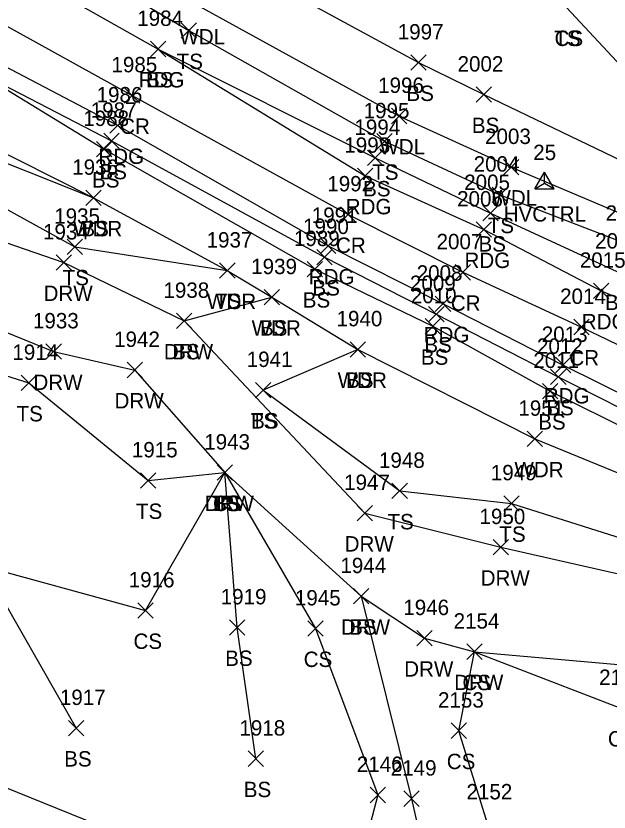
# Model space of a CAD drawing. Extents: x 1512665 to 1513714, y 110636 to 112816.
# Drawn here: x 1512837.5 to 1512914.5, y 110765.6 to 110869.1 of the extents above; entities that cross this region are included whole.
import ezdxf

# ---------------------------------------------------------------- set-up
doc = ezdxf.new("R2010")
doc.units = 0
for name, color, linetype in [('C_A', 7, 'Continuous'), ('C_I', 7, 'Continuous'), ('CPSM', 7, 'Continuous'), ('L_A', 7, 'Continuous'), ('L_I', 7, 'Continuous'), ('L_TIC', 7, 'Continuous'), ('LAWA', 7, 'Continuous'), ('LELB', 7, 'Continuous'), ('LSOGP', 7, 'Continuous'), ('P_A', 7, 'Continuous'), ('P_I', 7, 'Continuous'), ('P_TIC', 7, 'Continuous'), ('PEU', 7, 'Continuous'), ('PRC', 7, 'Continuous'), ('R_A', 7, 'Continuous'), ('R_I', 7, 'Continuous'), ('R_TIC', 7, 'Continuous'), ('RDW', 7, 'Continuous')]:
    doc.layers.add(name, color=color, linetype=linetype)

msp = doc.modelspace()

# ---------------------------------------------------------------- linework, layer by layer
at = {"layer": 'CPSM'}
for p, q in [((1512904.88, 110846.67), (1512906.13, 110848.84)), ((1512907.38, 110846.67), (1512906.13, 110848.84)), ((1512906.13, 110847.4), (1512906.13, 110848.84)), ((1512904.88, 110846.67), (1512906.13, 110847.4)), ((1512906.13, 110847.4), (1512906.13, 110847.4)), ((1512906.13, 110847.4), (1512907.38, 110846.67)), ((1512904.88, 110846.67), (1512907.38, 110846.67))]:
    msp.add_line(p, q, dxfattribs=at)
at = {"layer": 'L_TIC'}
for points in [[(1512858.93, 110866.23), (1512860.93, 110868.23)], [(1512860.93, 110866.23), (1512858.93, 110868.23)], [(1512854.92, 110863.84), (1512856.92, 110865.84)], [(1512856.92, 110863.84), (1512854.92, 110865.84)], [(1512888.75, 110862.08), (1512890.75, 110864.08)], [(1512890.75, 110862.08), (1512888.75, 110864.08)], [(1512897.25, 110857.91), (1512899.25, 110859.91)], [(1512899.25, 110857.91), (1512897.25, 110859.91)], [(1512886.26, 110855.13), (1512888.26, 110857.13)], [(1512888.26, 110855.13), (1512886.26, 110857.13)], [(1512848.87, 110851.9), (1512850.87, 110853.9)], [(1512850.87, 110851.9), (1512848.87, 110853.9)], [(1512884.33, 110851.84), (1512886.33, 110853.84)], [(1512886.33, 110851.84), (1512884.33, 110853.84)], [(1512847.91, 110850.83), (1512849.91, 110852.83)], [(1512849.91, 110850.83), (1512847.91, 110852.83)], [(1512883.12, 110849.68), (1512885.12, 110851.68)], [(1512885.12, 110849.68), (1512883.12, 110851.68)], [(1512900.81, 110848.49), (1512902.81, 110850.49)], [(1512902.81, 110848.49), (1512900.81, 110850.49)], [(1512846.52, 110844.49), (1512848.52, 110846.49)], [(1512848.52, 110844.49), (1512846.52, 110846.49)], [(1512846.52, 110844.49), (1512848.52, 110846.49)], [(1512848.52, 110844.49), (1512846.52, 110846.49)], [(1512899.34, 110844.9), (1512901.34, 110846.9)], [(1512901.34, 110844.9), (1512899.34, 110846.9)], [(1512898.11, 110842.51), (1512900.11, 110844.51)], [(1512900.11, 110842.51), (1512898.11, 110844.51)], [(1512844.12, 110838.12), (1512846.12, 110840.12)], [(1512846.12, 110838.12), (1512844.12, 110840.12)], [(1512876.54, 110836.79), (1512878.54, 110838.79)], [(1512878.54, 110836.79), (1512876.54, 110838.79)], [(1512863.92, 110835.03), (1512865.92, 110837.03)], [(1512865.92, 110835.03), (1512863.92, 110837.03)], [(1512863.92, 110835.03), (1512865.92, 110837.03)], [(1512865.92, 110835.03), (1512863.92, 110837.03)], [(1512875.28, 110835.22), (1512877.28, 110837.22)], [(1512877.28, 110835.22), (1512875.28, 110837.22)], [(1512869.72, 110831.57), (1512871.72, 110833.57)], [(1512871.72, 110831.57), (1512869.72, 110833.57)], [(1512869.72, 110831.57), (1512871.72, 110833.57)], [(1512871.72, 110831.57), (1512869.72, 110833.57)], [(1512858.31, 110828.49), (1512860.31, 110830.49)], [(1512860.31, 110828.49), (1512858.31, 110830.49)], [(1512891.07, 110829.38), (1512893.07, 110831.38)], [(1512893.07, 110829.38), (1512891.07, 110831.38)], [(1512890.62, 110827.79), (1512892.62, 110829.79)], [(1512892.62, 110827.79), (1512890.62, 110829.79)], [(1512880.89, 110824.79), (1512882.89, 110826.79)], [(1512882.89, 110824.79), (1512880.89, 110826.79)], [(1512880.89, 110824.79), (1512882.89, 110826.79)], [(1512882.89, 110824.79), (1512880.89, 110826.79)], [(1512906.92, 110821.22), (1512908.92, 110823.22)], [(1512908.92, 110821.22), (1512906.92, 110823.22)], [(1512838.13, 110820.43), (1512840.13, 110822.43)], [(1512840.13, 110820.43), (1512838.13, 110822.43)], [(1512868.57, 110819.5), (1512870.57, 110821.5)], [(1512870.57, 110819.5), (1512868.57, 110821.5)], [(1512868.57, 110819.5), (1512870.57, 110821.5)], [(1512870.57, 110819.5), (1512868.57, 110821.5)], [(1512905.87, 110819.37), (1512907.87, 110821.37)], [(1512907.87, 110819.37), (1512905.87, 110821.37)], [(1512903.86, 110813.16), (1512905.86, 110815.16)], [(1512905.86, 110813.16), (1512903.86, 110815.16)], [(1512863.61, 110808.77), (1512865.61, 110810.77)], [(1512865.61, 110808.77), (1512863.61, 110810.77)], [(1512863.61, 110808.77), (1512865.61, 110810.77)], [(1512865.61, 110808.77), (1512863.61, 110810.77)], [(1512863.61, 110808.77), (1512865.61, 110810.77)], [(1512865.61, 110808.77), (1512863.61, 110810.77)], [(1512853.65, 110807.75), (1512855.65, 110809.75)], [(1512855.65, 110807.75), (1512853.65, 110809.75)], [(1512886.31, 110806.39), (1512888.31, 110808.39)], [(1512888.31, 110806.39), (1512886.31, 110808.39)], [(1512900.85, 110804.77), (1512902.85, 110806.77)], [(1512902.85, 110804.77), (1512900.85, 110806.77)], [(1512881.31, 110792.7), (1512883.31, 110794.7)], [(1512883.31, 110792.7), (1512881.31, 110794.7)], [(1512853.29, 110790.85), (1512855.29, 110792.85)], [(1512855.29, 110790.85), (1512853.29, 110792.85)], [(1512865.19, 110788.64), (1512867.19, 110790.64)], [(1512867.19, 110788.64), (1512865.19, 110790.64)], [(1512875.39, 110788.5), (1512877.39, 110790.5)], [(1512877.39, 110788.5), (1512875.39, 110790.5)], [(1512896.02, 110785.49), (1512898.02, 110787.49)], [(1512898.02, 110785.49), (1512896.02, 110787.49)], [(1512844.29, 110775.56), (1512846.29, 110777.56)], [(1512846.29, 110775.56), (1512844.29, 110777.56)], [(1512893.99, 110775.22), (1512895.99, 110777.22)], [(1512895.99, 110775.22), (1512893.99, 110777.22)], [(1512867.62, 110771.58), (1512869.62, 110773.58)], [(1512869.62, 110771.58), (1512867.62, 110773.58)], [(1512883.49, 110766.86), (1512885.49, 110768.86)], [(1512885.49, 110766.86), (1512883.49, 110768.86)], [(1512887.86, 110766.38), (1512889.86, 110768.38)], [(1512889.86, 110766.38), (1512887.86, 110768.38)]]:
    msp.add_lwpolyline(points, dxfattribs=at)
at = {"layer": 'LAWA'}
for points in [[(1512760.33, 110918.9), (1512789.47, 110902.15), (1512814, 110894.65), (1512829.43, 110887.29), (1512830.77, 110885.04), (1512838.88, 110882.65), (1512840.96, 110881.39), (1512843.66, 110878.58), (1512861.27, 110870.43), (1512887.26, 110856.13), (1512901.81, 110849.49), (1512918.08, 110842.57)], [(1512680.49, 110906.6), (1512690.44, 110907.09), (1512704.39, 110894.87), (1512725.94, 110900.33), (1512738.13, 110894.41), (1512761.21, 110888.67), (1512781.15, 110881.47), (1512810.21, 110864.84), (1512817.69, 110861.88), (1512832.48, 110853.08), (1512847.52, 110845.49), (1512864.92, 110836.03), (1512870.72, 110832.57), (1512881.89, 110825.79), (1512904.86, 110814.16), (1512921.13, 110807.47)]]:
    msp.add_lwpolyline(points, dxfattribs=at)
at = {"layer": 'LELB'}
for points in [[(1512700.68, 110948.39), (1512702.88, 110937.76), (1512707.7, 110928.25), (1512715.73, 110919.82), (1512729.36, 110912.4), (1512733.11, 110910.82), (1512749.56, 110901.48), (1512765.39, 110894.4), (1512774.13, 110890.87), (1512779.73, 110888.58), (1512784.33, 110885.95), (1512807.05, 110874.73), (1512832.03, 110862.15), (1512849.87, 110852.9), (1512877.54, 110837.79), (1512892.07, 110830.38), (1512907.92, 110822.22), (1512921.56, 110815.36), (1512936.61, 110807.63), (1512945.8, 110795.18), (1512949.9, 110789.74), (1512950.99, 110781.57)], [(1512721.89, 110948.79), (1512722.5, 110942.68), (1512730.74, 110933.36), (1512741.91, 110924.63), (1512760.33, 110918.9), (1512788.26, 110897.8), (1512812.95, 110889.37), (1512823.67, 110884.08), (1512829.43, 110887.29), (1512828.6, 110891.88), (1512837.52, 110889.39), (1512842.18, 110886.4), (1512840.96, 110881.39), (1512842.49, 110877.54), (1512859.93, 110867.23), (1512885.33, 110852.84), (1512900.34, 110845.9), (1512916.83, 110839.51), (1512931.35, 110831.64), (1512947.32, 110821.38)], [(1512842.76, 110906.57), (1512862.48, 110896.3), (1512875.48, 110891.21), (1512894.67, 110874.81), (1512908.99, 110870.23), (1512923.21, 110854.93), (1512926.27, 110845.46)], [(1512685.37, 110901.62), (1512704.39, 110894.87), (1512721.83, 110890.38), (1512736.95, 110883.29), (1512758.15, 110875.39), (1512778.26, 110867.83), (1512805.48, 110853.5), (1512829.24, 110847.86), (1512845.12, 110839.12), (1512864.92, 110836.03)], [(1512738.13, 110894.41), (1512760.68, 110883.09), (1512779.76, 110877.43), (1512809.28, 110861.94), (1512816.23, 110858.7), (1512830.12, 110852.43), (1512847.52, 110845.49)], [(1512847.53, 110891.12), (1512864.84, 110876.65), (1512889.75, 110863.08), (1512898.25, 110858.91), (1512926.27, 110845.46), (1512938.49, 110838.55)], [(1512698.23, 110870.27), (1512729.45, 110862.45), (1512749.63, 110850.69), (1512777.7, 110834.64), (1512793.92, 110831.75), (1512815.55, 110826.53), (1512828.48, 110824.79), (1512839.13, 110821.43), (1512854.65, 110808.75), (1512864.61, 110809.77)], [(1512855.92, 110864.84), (1512884.12, 110850.68), (1512899.11, 110843.51), (1512915.53, 110835.9), (1512929.01, 110828.77), (1512945.8, 110819.12), (1512965.77, 110809.05)], [(1512832.03, 110862.15), (1512848.91, 110851.83), (1512876.28, 110836.22), (1512891.62, 110828.79), (1512906.87, 110820.37), (1512921.49, 110813.14), (1512935.76, 110805.39), (1512943.83, 110794.81), (1512945.64, 110788.65)], [(1512859.31, 110829.49), (1512870.72, 110832.57)], [(1512793.92, 110831.75), (1512810.04, 110815.8), (1512828.82, 110806.75), (1512833.23, 110797.62), (1512845.29, 110776.56)], [(1512881.89, 110825.79), (1512869.57, 110820.5)], [(1512869.57, 110820.5), (1512887.31, 110807.39), (1512901.85, 110805.77), (1512924.72, 110798.5), (1512939.47, 110793.1)], [(1512833.23, 110797.62), (1512854.29, 110791.85), (1512864.61, 110809.77), (1512876.39, 110789.5), (1512884.49, 110767.86), (1512880.03, 110750.81)], [(1512868.62, 110772.58), (1512866.19, 110789.64), (1512864.61, 110809.77)], [(1512882.31, 110793.7), (1512888.86, 110767.38), (1512893.27, 110747.85)], [(1512902.91, 110747.2), (1512898.68, 110764.29), (1512894.99, 110776.22), (1512897.02, 110786.49), (1512915.92, 110779.17), (1512918.44, 110768.09), (1512924.56, 110757.29), (1512930.94, 110739.07), (1512912.47, 110736.35), (1512889.78, 110732.88)]]:
    msp.add_lwpolyline(points, dxfattribs=at)
at = {"layer": 'LSOGP'}
msp.add_lwpolyline([(1512677.75, 110879.68), (1512694.93, 110847.53), (1512720.01, 110832.5), (1512744.42, 110818.94), (1512769.04, 110811.74), (1512784.16, 110806.73), (1512800.09, 110794.66), (1512819.62, 110775.51), (1512859.02, 110759.58), (1512880.03, 110750.81), (1512889.78, 110732.88), (1512896.82, 110720.33), (1512918.08, 110708.27)], dxfattribs=at)
at = {"layer": 'P_TIC'}
for points in [[(1512854.92, 110863.84), (1512856.92, 110865.84)], [(1512856.92, 110863.84), (1512854.92, 110865.84)], [(1512851.56, 110857.81), (1512853.56, 110859.81)], [(1512853.56, 110857.81), (1512851.56, 110859.81)], [(1512849.68, 110853.9), (1512851.68, 110855.9)], [(1512851.68, 110853.9), (1512849.68, 110855.9)], [(1512881.82, 110847.35), (1512883.82, 110849.35)], [(1512883.82, 110847.35), (1512881.82, 110849.35)], [(1512879.61, 110842.33), (1512881.61, 110844.33)], [(1512881.61, 110842.33), (1512879.61, 110844.33)], [(1512897.24, 110840.37), (1512899.24, 110842.37)], [(1512899.24, 110840.37), (1512897.24, 110842.37)], [(1512877.02, 110838.24), (1512879.02, 110840.24)], [(1512879.02, 110838.24), (1512877.02, 110840.24)], [(1512894.52, 110834.81), (1512896.52, 110836.81)], [(1512896.52, 110834.81), (1512894.52, 110836.81)], [(1512912.49, 110832.4), (1512914.49, 110834.4)], [(1512914.49, 110832.4), (1512912.49, 110834.4)], [(1512891.94, 110830.72), (1512893.94, 110832.72)], [(1512893.94, 110830.72), (1512891.94, 110832.72)], [(1512909.92, 110827.7), (1512911.92, 110829.7)], [(1512911.92, 110827.7), (1512909.92, 110829.7)], [(1512907.54, 110822.76), (1512909.54, 110824.76)], [(1512909.54, 110822.76), (1512907.54, 110824.76)]]:
    msp.add_lwpolyline(points, dxfattribs=at)
at = {"layer": 'PEU'}
for points in [[(1512701.92, 111049.69), (1512700.27, 111027.69), (1512701.57, 110993.78), (1512707.63, 110973.74), (1512708.97, 110956.47), (1512713.57, 110946.9), (1512719.22, 110936.54), (1512726.89, 110929.38), (1512741.61, 110919.6), (1512758.16, 110912.38), (1512787.35, 110896), (1512813.05, 110887.98), (1512838.37, 110874.78), (1512855.92, 110864.84), (1512882.82, 110848.35), (1512898.24, 110841.37), (1512913.49, 110833.4), (1512927.92, 110827.38), (1512944.46, 110817.21), (1512962.88, 110803.83), (1512982.13, 110789.05), (1512997.25, 110777.45), (1513011.32, 110770.56), (1513024, 110765.99)], [(1512687.75, 111048.12), (1512689.18, 111024.57), (1512692.04, 110992.51), (1512695.11, 110971.67), (1512700.68, 110948.39), (1512706.36, 110937.56), (1512711.03, 110929.61), (1512717.58, 110922.71), (1512730.52, 110913.86), (1512733.94, 110912.11), (1512750.23, 110902.86), (1512766.31, 110896.48), (1512784.35, 110887.76), (1512808.18, 110876.47), (1512833.24, 110864.02), (1512850.68, 110854.9), (1512878.02, 110839.24), (1512892.94, 110831.72), (1512908.54, 110823.76), (1512922.46, 110816.85)]]:
    msp.add_lwpolyline(points, dxfattribs=at)
at = {"layer": 'PRC'}
msp.add_lwpolyline([(1512693.67, 111049.35), (1512695.61, 111024.36), (1512696.79, 110993.28), (1512701.08, 110972.95), (1512704.1, 110953.94), (1512709.81, 110942.45), (1512716.01, 110931.96), (1512724.47, 110925.17), (1512739.89, 110914.85), (1512755.51, 110906.44), (1512786.55, 110892.54), (1512810.31, 110881.66), (1512835.15, 110868.41), (1512852.56, 110858.81), (1512880.61, 110843.33), (1512895.52, 110835.81), (1512910.92, 110828.7), (1512924.7, 110822.05)], dxfattribs=at)
at = {"layer": 'R_TIC'}
for points in [[(1512842.68, 110836.08), (1512844.68, 110838.08)], [(1512844.68, 110836.08), (1512842.68, 110838.08)], [(1512858.31, 110828.49), (1512860.31, 110830.49)], [(1512860.31, 110828.49), (1512858.31, 110830.49)], [(1512841.36, 110824.52), (1512843.36, 110826.52)], [(1512843.36, 110824.52), (1512841.36, 110826.52)], [(1512851.9, 110822.11), (1512853.9, 110824.11)], [(1512853.9, 110822.11), (1512851.9, 110824.11)], [(1512863.61, 110808.77), (1512865.61, 110810.77)], [(1512865.61, 110808.77), (1512863.61, 110810.77)], [(1512881.79, 110803.51), (1512883.79, 110805.51)], [(1512883.79, 110803.51), (1512881.79, 110805.51)], [(1512899.46, 110799.08), (1512901.46, 110801.08)], [(1512901.46, 110799.08), (1512899.46, 110801.08)], [(1512881.31, 110792.7), (1512883.31, 110794.7)], [(1512883.31, 110792.7), (1512881.31, 110794.7)], [(1512889.53, 110787.25), (1512891.53, 110789.25)], [(1512891.53, 110787.25), (1512889.53, 110789.25)], [(1512896.02, 110785.49), (1512898.02, 110787.49)], [(1512898.02, 110785.49), (1512896.02, 110787.49)]]:
    msp.add_lwpolyline(points, dxfattribs=at)
at = {"layer": 'RDW'}
for points in [[(1512678.69, 110893.12), (1512705.91, 110885.74), (1512730.91, 110879.48), (1512757.28, 110870.83), (1512775.98, 110863.85), (1512803.62, 110850.37), (1512827.04, 110842.82), (1512843.68, 110837.08), (1512859.31, 110829.49), (1512882.79, 110804.51), (1512900.46, 110800.08), (1512923.2, 110794.9)], [(1512677.75, 110879.68), (1512702.96, 110877.46), (1512731.26, 110871.04), (1512755.65, 110862.16), (1512771.64, 110855.39), (1512800.14, 110841.72), (1512826.02, 110832.15), (1512842.36, 110825.52), (1512852.9, 110823.11), (1512864.61, 110809.77), (1512882.31, 110793.7), (1512890.53, 110788.25), (1512897.02, 110786.49), (1512918.65, 110784.55)]]:
    msp.add_lwpolyline(points, dxfattribs=at)

# ---------------------------------------------------------------- texts
at = {"layer": 'C_A'}
msp.add_text('HVCTRL', height=2, dxfattribs=at).set_placement((1512900.82, 110842.4))
at = {"layer": 'C_I'}
msp.add_text('25', height=2, dxfattribs=at).set_placement((1512904.66, 110850.4))
at = {"layer": 'L_A'}
for s, p in [('WDL', (1512858.69, 110865.43)), ('TS', (1512907.4, 110865.23)), ('CS', (1512907.43, 110865.23)), ('TS', (1512858.34, 110862.23)), ('BS', (1512854.36, 110859.84)), ('BS', (1512888.19, 110858.08)), ('BS', (1512896.69, 110853.91)), ('WDL', (1512884.67, 110851.13)), ('BS', (1512848.31, 110847.9)), ('TS', (1512883.74, 110847.84)), ('BS', (1512847.35, 110846.83)), ('BS', (1512882.56, 110845.68)), ('WDL', (1512899.23, 110844.49)), ('TS', (1512898.75, 110840.9)), ('WDR', (1512844.88, 110840.49)), ('BS', (1512845.96, 110840.49)), ('BS', (1512897.55, 110838.51)), ('TS', (1512843.53, 110834.12)), ('BS', (1512875.98, 110832.79)), ('WDR', (1512862.28, 110831.03)), ('TS', (1512863.33, 110831.03)), ('BS', (1512874.72, 110831.22)), ('BS', (1512913.97, 110830.9)), ('WDR', (1512868.08, 110827.57)), ('BS', (1512869.16, 110827.57)), ('BS', (1512890.51, 110825.38)), ('BS', (1512857.76, 110824.49)), ('BS', (1512890.06, 110823.79)), ('WDR', (1512879.26, 110820.79)), ('BS', (1512880.34, 110820.79)), ('BS', (1512906.36, 110817.22)), ('TS', (1512837.54, 110816.43)), ('TS', (1512867.98, 110815.5)), ('BS', (1512868.01, 110815.5)), ('BS', (1512905.31, 110815.37)), ('WDR', (1512902.22, 110809.16)), ('TS', (1512863.02, 110804.77)), ('CS', (1512863.06, 110804.77)), ('BS', (1512863.06, 110804.77)), ('TS', (1512853.06, 110803.75)), ('TS', (1512885.72, 110802.39)), ('TS', (1512900.26, 110800.77)), ('BS', (1512880.75, 110788.7)), ('CS', (1512852.73, 110786.85)), ('BS', (1512864.64, 110784.64)), ('CS', (1512874.84, 110784.5)), ('CS', (1512895.46, 110781.49)), ('CS', (1512914.36, 110774.17)), ('BS', (1512843.73, 110771.56)), ('CS', (1512893.43, 110771.22)), ('BS', (1512867.06, 110767.58))]:
    msp.add_text(s, height=2, dxfattribs=at).set_placement(p)
at = {"layer": 'L_I'}
for s, p in [('1984', (1512853.22, 110867.84)), ('1997', (1512887.06, 110866.08)), ('2002', (1512894.83, 110861.91)), ('1996', (1512884.51, 110859.13)), ('1987', (1512847.18, 110855.9)), ('1995', (1512882.63, 110855.84)), ('1988', (1512846.21, 110854.83)), ('1994', (1512881.43, 110853.68)), ('2003', (1512898.4, 110852.49)), ('1936', (1512844.77, 110848.49)), ('1936', (1512844.77, 110848.49)), ('2004', (1512896.92, 110848.9)), ('2005', (1512895.69, 110846.51)), ('1935', (1512842.43, 110842.12)), ('2017', (1512914.06, 110842.51)), ('1990', (1512874.76, 110840.79)), ('1937', (1512862.23, 110839.03)), ('1937', (1512862.23, 110839.03)), ('1989', (1512873.58, 110839.22)), ('2016', (1512912.7, 110838.9)), ('1939', (1512868.02, 110835.57)), ('1939', (1512868.02, 110835.57)), ('2009', (1512888.64, 110833.38)), ('1938', (1512856.62, 110832.49)), ('2010', (1512888.76, 110831.79)), ('1940', (1512879.11, 110828.79)), ('1940', (1512879.11, 110828.79)), ('1914', (1512837, 110824.43)), ('2012', (1512905.15, 110825.22)), ('1941', (1512867.44, 110823.5)), ('1941', (1512867.44, 110823.5)), ('2011', (1512904.67, 110823.37)), ('1951', (1512902.73, 110817.16)), ('1943', (1512861.92, 110812.77)), ('1943', (1512861.92, 110812.77)), ('1943', (1512861.92, 110812.77)), ('1915', (1512852.52, 110811.75)), ('1948', (1512884.62, 110810.39)), ('1949', (1512899.15, 110808.77)), ('1944', (1512879.61, 110796.7)), ('1916', (1512852.11, 110794.85)), ('1919', (1512864.06, 110792.64)), ('1945', (1512873.7, 110792.5)), ('2154', (1512894.32, 110789.49)), ('2155', (1512913.22, 110782.17)), ('1917', (1512843.17, 110779.56)), ('2153', (1512892.29, 110779.22)), ('1918', (1512866.49, 110775.58)), ('2146', (1512881.74, 110770.86)), ('2149', (1512886.15, 110770.38)), ('2152', (1512895.99, 110767.29))]:
    msp.add_text(s, height=2, dxfattribs=at).set_placement(p)
at = {"layer": 'P_A'}
for s, p in [('RDG', (1512853.41, 110859.84)), ('CR', (1512850.99, 110853.81)), ('RDG', (1512848.17, 110849.9)), ('RDG', (1512880.3, 110843.35)), ('CR', (1512879.04, 110838.33)), ('RDG', (1512895.73, 110836.37)), ('RDG', (1512875.5, 110834.24)), ('CR', (1512893.95, 110830.81)), ('RDG', (1512910.97, 110828.4)), ('RDG', (1512890.43, 110826.72)), ('CR', (1512909.35, 110823.7)), ('RDG', (1512906.03, 110818.76))]:
    msp.add_text(s, height=2, dxfattribs=at).set_placement(p)
at = {"layer": 'P_I'}
for s, p in [('1984', (1512853.22, 110867.84)), ('1985', (1512849.87, 110861.81)), ('1986', (1512847.94, 110857.9)), ('1993', (1512880.12, 110851.35)), ('1992', (1512877.91, 110846.33)), ('2006', (1512894.77, 110844.37)), ('1991', (1512875.89, 110842.24)), ('2007', (1512892.1, 110838.81)), ('2015', (1512910.71, 110836.4)), ('2008', (1512889.52, 110834.72)), ('2014', (1512908.15, 110831.7)), ('2013', (1512905.77, 110826.76))]:
    msp.add_text(s, height=2, dxfattribs=at).set_placement(p)
at = {"layer": 'R_A'}
for p in [(1512841.05, 110832.08), (1512856.68, 110824.49), (1512839.73, 110820.52), (1512850.27, 110818.11), (1512861.99, 110804.77), (1512880.16, 110799.51), (1512897.83, 110795.08), (1512879.68, 110788.7), (1512887.9, 110783.25), (1512894.39, 110781.49)]:
    msp.add_text('DRW', height=2, dxfattribs=at).set_placement(p)
at = {"layer": 'R_I'}
for s, p in [('1934', (1512840.98, 110840.08)), ('1938', (1512856.62, 110832.49)), ('1933', (1512839.67, 110828.52)), ('1942', (1512850.21, 110826.11)), ('1943', (1512861.92, 110812.77)), ('1947', (1512880.09, 110807.51)), ('1950', (1512897.68, 110803.08)), ('1944', (1512879.61, 110796.7)), ('1946', (1512887.78, 110791.25)), ('2154', (1512894.32, 110789.49))]:
    msp.add_text(s, height=2, dxfattribs=at).set_placement(p)

doc.saveas('drawing.dxf')
